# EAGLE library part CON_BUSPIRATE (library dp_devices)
PIN HEADER
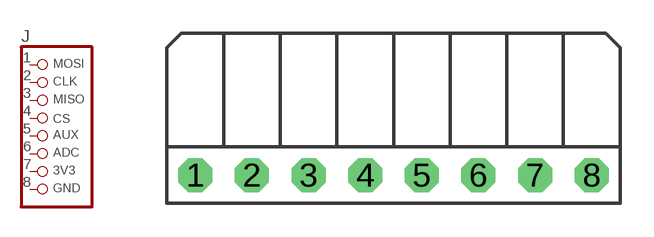
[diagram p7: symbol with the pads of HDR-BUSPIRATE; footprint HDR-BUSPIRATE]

Designator prefix J

## CON_BUSPIRATE  [HDR-BUSPIRATE]
1  1  pas
2  2  pas
3  3  pas
4  4  pas
5  5  pas
6  6  pas
7  7  pas
8  8  pas

## Footprint HDR-BUSPIRATE (pad centres in mm)
PIN HEADER
drill 1.016 octagon: 1 -8.89,0; 2 -6.35,0; 3 -3.81,0; 4 -1.27,0; 5 1.27,0; 6 3.81,0; 7 6.35,0; 8 8.89,0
